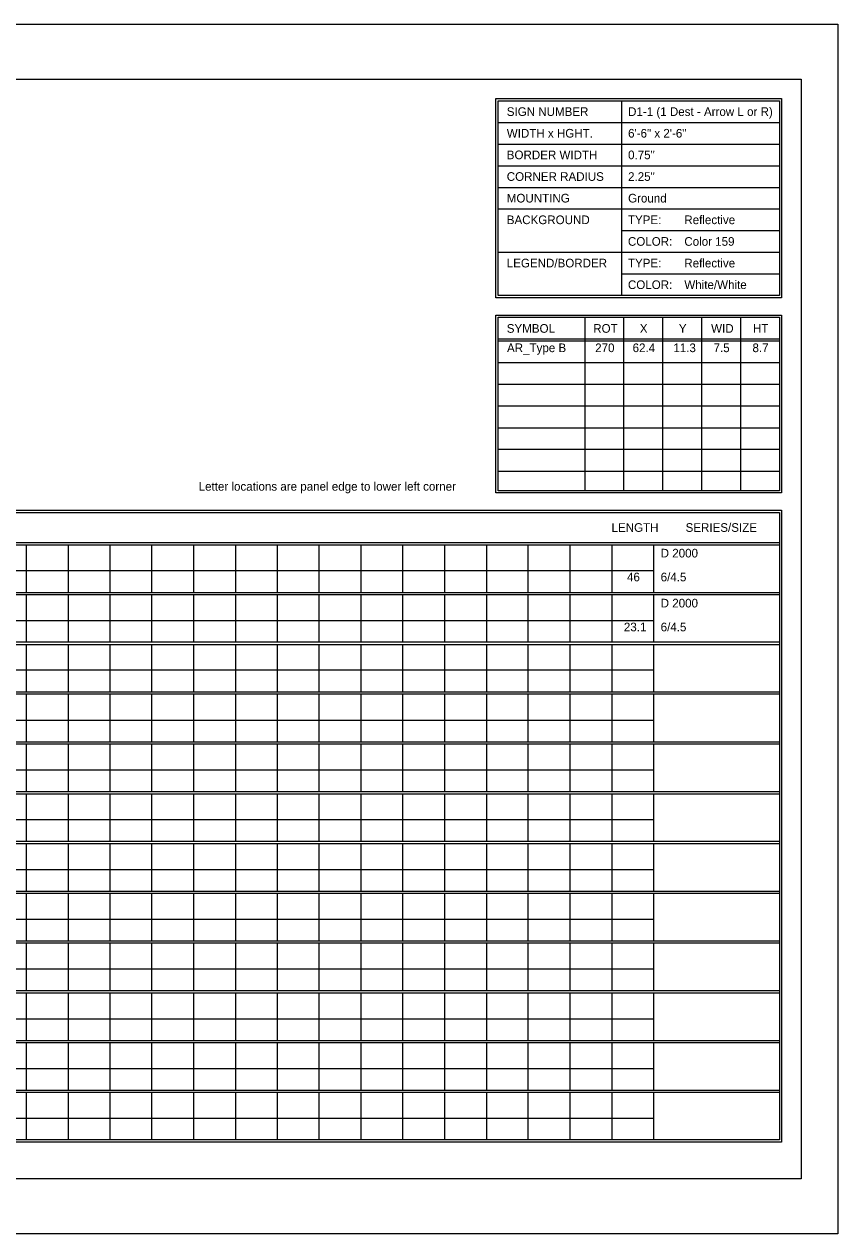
# Model space of a CAD drawing. Extents: x 1806251 to 1809821, y 414895 to 422886.
# Drawn here: x 1809679.34 to 1809684.89, y 415065.97 to 415074.23 of the extents above; entities that cross this region are included whole.
import ezdxf

# ---------------------------------------------------------------- set-up
doc = ezdxf.new("R2010")
doc.units = 0
doc.layers.add('GSSHT', color=7, linetype='Continuous')

msp = doc.modelspace()

# ---------------------------------------------------------------- linework, layer by layer
at = {"layer": 'GSSHT'}
for p, q in [((1809672.1349, 415074.2262), (1809684.8891, 415074.2262)), ((1809684.8891, 415074.2262), (1809684.8891, 415065.9725)), ((1809683.4126, 415073.7035), (1809683.4126, 415072.3747)), ((1809682.571, 415073.5559), (1809684.4905, 415073.5559)), ((1809682.571, 415073.4082), (1809684.4905, 415073.4082)), ((1809682.571, 415073.2606), (1809684.4905, 415073.2606)), ((1809682.571, 415073.1129), (1809684.4905, 415073.1129)), ((1809682.571, 415072.9653), (1809684.4905, 415072.9653)), ((1809683.4126, 415072.8176), (1809684.4905, 415072.8176)), ((1809682.571, 415072.67), (1809684.4905, 415072.67)), ((1809683.4126, 415072.5223), (1809684.4905, 415072.5223)), ((1809683.1616, 415072.227), (1809683.1616, 415071.0428)), ((1809683.4274, 415072.227), (1809683.4274, 415071.0428)), ((1809683.6931, 415072.227), (1809683.6931, 415071.0428)), ((1809683.9589, 415072.227), (1809683.9589, 415071.0428)), ((1809684.2247, 415072.227), (1809684.2247, 415071.0428)), ((1809682.571, 415072.0794), (1809684.4905, 415072.0794)), ((1809682.571, 415072.0646), (1809684.4905, 415072.0646)), ((1809682.571, 415071.9169), (1809684.4905, 415071.9169)), ((1809682.571, 415071.7693), (1809684.4905, 415071.7693)), ((1809682.571, 415071.6216), (1809684.4905, 415071.6216)), ((1809682.571, 415071.471), (1809684.4905, 415071.471)), ((1809682.571, 415071.3263), (1809684.4905, 415071.3263)), ((1809682.571, 415071.1757), (1809684.4905, 415071.1757)), ((1809672.7816, 415070.6885), (1809684.4905, 415070.6885)), ((1809672.7816, 415070.6737), (1809684.4905, 415070.6737)), ((1809679.3492, 415070.6737), (1809679.3492, 415070.3489)), ((1809679.6357, 415070.6737), (1809679.6357, 415070.3489)), ((1809679.9221, 415070.6737), (1809679.9221, 415070.3489)), ((1809680.2056, 415070.6737), (1809680.2056, 415070.3489)), ((1809680.492, 415070.6737), (1809680.492, 415070.3489)), ((1809680.7785, 415070.6737), (1809680.7785, 415070.3489)), ((1809681.062, 415070.6737), (1809681.062, 415070.3489)), ((1809681.3484, 415070.6737), (1809681.3484, 415070.3489)), ((1809681.6349, 415070.6737), (1809681.6349, 415070.3489)), ((1809681.9184, 415070.6737), (1809681.9184, 415070.3489)), ((1809682.2048, 415070.6737), (1809682.2048, 415070.3489)), ((1809682.4913, 415070.6737), (1809682.4913, 415070.3489)), ((1809682.7747, 415070.6737), (1809682.7747, 415070.3489)), ((1809683.0612, 415070.6737), (1809683.0612, 415070.3489)), ((1809683.3476, 415070.6737), (1809683.3476, 415070.3489)), ((1809683.6311, 415070.6737), (1809683.6311, 415070.3489)), ((1809672.7816, 415070.4995), (1809683.6311, 415070.4995)), ((1809672.7816, 415070.3489), (1809684.4905, 415070.3489)), ((1809672.7816, 415070.3341), (1809684.4905, 415070.3341)), ((1809679.3492, 415070.3341), (1809679.3492, 415070.0122)), ((1809679.6357, 415070.3341), (1809679.6357, 415070.0122)), ((1809679.9221, 415070.3341), (1809679.9221, 415070.0122)), ((1809680.2056, 415070.3341), (1809680.2056, 415070.0122)), ((1809680.492, 415070.3341), (1809680.492, 415070.0122)), ((1809680.7785, 415070.3341), (1809680.7785, 415070.0122)), ((1809681.062, 415070.3341), (1809681.062, 415070.0122)), ((1809681.3484, 415070.3341), (1809681.3484, 415070.0122)), ((1809681.6349, 415070.3341), (1809681.6349, 415070.0122)), ((1809681.9184, 415070.3341), (1809681.9184, 415070.0122)), ((1809682.2048, 415070.3341), (1809682.2048, 415070.0122)), ((1809682.4913, 415070.3341), (1809682.4913, 415070.0122)), ((1809682.7747, 415070.3341), (1809682.7747, 415070.0122)), ((1809683.0612, 415070.3341), (1809683.0612, 415070.0122)), ((1809683.3476, 415070.3341), (1809683.3476, 415070.0122)), ((1809683.6311, 415070.3341), (1809683.6311, 415070.0122)), ((1809672.7816, 415070.1569), (1809683.6311, 415070.1569)), ((1809672.7816, 415070.0122), (1809684.4905, 415070.0122)), ((1809672.7816, 415069.9945), (1809684.4905, 415069.9945)), ((1809679.3492, 415069.9945), (1809679.3492, 415069.6697)), ((1809679.6357, 415069.9945), (1809679.6357, 415069.6697)), ((1809679.9221, 415069.9945), (1809679.9221, 415069.6697)), ((1809680.2056, 415069.9945), (1809680.2056, 415069.6697)), ((1809680.492, 415069.9945), (1809680.492, 415069.6697)), ((1809680.7785, 415069.9945), (1809680.7785, 415069.6697)), ((1809681.062, 415069.9945), (1809681.062, 415069.6697)), ((1809681.3484, 415069.9945), (1809681.3484, 415069.6697)), ((1809681.6349, 415069.9945), (1809681.6349, 415069.6697)), ((1809681.9184, 415069.9945), (1809681.9184, 415069.6697)), ((1809682.2048, 415069.9945), (1809682.2048, 415069.6697)), ((1809682.4913, 415069.9945), (1809682.4913, 415069.6697)), ((1809682.7747, 415069.9945), (1809682.7747, 415069.6697)), ((1809683.0612, 415069.9945), (1809683.0612, 415069.6697)), ((1809683.3476, 415069.9945), (1809683.3476, 415069.6697)), ((1809683.6311, 415069.9945), (1809683.6311, 415069.6697)), ((1809672.7816, 415069.8203), (1809683.6311, 415069.8203)), ((1809672.7816, 415069.6697), (1809684.4905, 415069.6697)), ((1809672.7816, 415069.6579), (1809684.4905, 415069.6579)), ((1809679.3492, 415069.6579), (1809679.3492, 415069.3301)), ((1809679.6357, 415069.6579), (1809679.6357, 415069.3301)), ((1809679.9221, 415069.6579), (1809679.9221, 415069.3301)), ((1809680.2056, 415069.6579), (1809680.2056, 415069.3301)), ((1809680.492, 415069.6579), (1809680.492, 415069.3301)), ((1809680.7785, 415069.6579), (1809680.7785, 415069.3301)), ((1809681.062, 415069.6579), (1809681.062, 415069.3301)), ((1809681.3484, 415069.6579), (1809681.3484, 415069.3301)), ((1809681.6349, 415069.6579), (1809681.6349, 415069.3301)), ((1809681.9184, 415069.6579), (1809681.9184, 415069.3301)), ((1809682.2048, 415069.6579), (1809682.2048, 415069.3301)), ((1809682.4913, 415069.6579), (1809682.4913, 415069.3301)), ((1809682.7747, 415069.6579), (1809682.7747, 415069.3301)), ((1809683.0612, 415069.6579), (1809683.0612, 415069.3301)), ((1809683.3476, 415069.6579), (1809683.3476, 415069.3301)), ((1809683.6311, 415069.6579), (1809683.6311, 415069.3301)), ((1809672.7816, 415069.4777), (1809683.6311, 415069.4777)), ((1809672.7816, 415069.3301), (1809684.4905, 415069.3301)), ((1809672.7816, 415069.3153), (1809684.4905, 415069.3153)), ((1809679.3492, 415069.3153), (1809679.3492, 415068.9905)), ((1809679.6357, 415069.3153), (1809679.6357, 415068.9905)), ((1809679.9221, 415069.3153), (1809679.9221, 415068.9905)), ((1809680.2056, 415069.3153), (1809680.2056, 415068.9905)), ((1809680.492, 415069.3153), (1809680.492, 415068.9905)), ((1809680.7785, 415069.3153), (1809680.7785, 415068.9905)), ((1809681.062, 415069.3153), (1809681.062, 415068.9905)), ((1809681.3484, 415069.3153), (1809681.3484, 415068.9905)), ((1809681.6349, 415069.3153), (1809681.6349, 415068.9905)), ((1809681.9184, 415069.3153), (1809681.9184, 415068.9905)), ((1809682.2048, 415069.3153), (1809682.2048, 415068.9905)), ((1809682.4913, 415069.3153), (1809682.4913, 415068.9905)), ((1809682.7747, 415069.3153), (1809682.7747, 415068.9905)), ((1809683.0612, 415069.3153), (1809683.0612, 415068.9905)), ((1809683.3476, 415069.3153), (1809683.3476, 415068.9905)), ((1809683.6311, 415069.3153), (1809683.6311, 415068.9905)), ((1809672.7816, 415069.1381), (1809683.6311, 415069.1381)), ((1809672.7816, 415068.9905), (1809684.4905, 415068.9905)), ((1809672.7816, 415068.9757), (1809684.4905, 415068.9757)), ((1809679.3492, 415068.9757), (1809679.3492, 415068.6509)), ((1809679.6357, 415068.9757), (1809679.6357, 415068.6509)), ((1809679.9221, 415068.9757), (1809679.9221, 415068.6509)), ((1809680.2056, 415068.9757), (1809680.2056, 415068.6509)), ((1809680.492, 415068.9757), (1809680.492, 415068.6509)), ((1809680.7785, 415068.9757), (1809680.7785, 415068.6509)), ((1809681.062, 415068.9757), (1809681.062, 415068.6509)), ((1809681.3484, 415068.9757), (1809681.3484, 415068.6509)), ((1809681.6349, 415068.9757), (1809681.6349, 415068.6509)), ((1809681.9184, 415068.9757), (1809681.9184, 415068.6509)), ((1809682.2048, 415068.9757), (1809682.2048, 415068.6509)), ((1809682.4913, 415068.9757), (1809682.4913, 415068.6509)), ((1809682.7747, 415068.9757), (1809682.7747, 415068.6509)), ((1809683.0612, 415068.9757), (1809683.0612, 415068.6509)), ((1809683.3476, 415068.9757), (1809683.3476, 415068.6509)), ((1809683.6311, 415068.9757), (1809683.6311, 415068.6509)), ((1809672.7816, 415068.7985), (1809683.6311, 415068.7985)), ((1809672.7816, 415068.6509), (1809684.4905, 415068.6509)), ((1809672.7816, 415068.6361), (1809684.4905, 415068.6361)), ((1809679.3492, 415068.6361), (1809679.3492, 415068.3113)), ((1809679.6357, 415068.6361), (1809679.6357, 415068.3113)), ((1809679.9221, 415068.6361), (1809679.9221, 415068.3113)), ((1809680.2056, 415068.6361), (1809680.2056, 415068.3113)), ((1809680.492, 415068.6361), (1809680.492, 415068.3113)), ((1809680.7785, 415068.6361), (1809680.7785, 415068.3113)), ((1809681.062, 415068.6361), (1809681.062, 415068.3113)), ((1809681.3484, 415068.6361), (1809681.3484, 415068.3113)), ((1809681.6349, 415068.6361), (1809681.6349, 415068.3113)), ((1809681.9184, 415068.6361), (1809681.9184, 415068.3113)), ((1809682.2048, 415068.6361), (1809682.2048, 415068.3113)), ((1809682.4913, 415068.6361), (1809682.4913, 415068.3113)), ((1809682.7747, 415068.6361), (1809682.7747, 415068.3113)), ((1809683.0612, 415068.6361), (1809683.0612, 415068.3113)), ((1809683.3476, 415068.6361), (1809683.3476, 415068.3113)), ((1809683.6311, 415068.6361), (1809683.6311, 415068.3113)), ((1809672.7816, 415068.4589), (1809683.6311, 415068.4589)), ((1809672.7816, 415068.3113), (1809684.4905, 415068.3113)), ((1809672.7816, 415068.2965), (1809684.4905, 415068.2965)), ((1809679.3492, 415068.2965), (1809679.3492, 415067.9717)), ((1809679.6357, 415068.2965), (1809679.6357, 415067.9717)), ((1809679.9221, 415068.2965), (1809679.9221, 415067.9717)), ((1809680.2056, 415068.2965), (1809680.2056, 415067.9717)), ((1809680.492, 415068.2965), (1809680.492, 415067.9717)), ((1809680.7785, 415068.2965), (1809680.7785, 415067.9717)), ((1809681.062, 415068.2965), (1809681.062, 415067.9717)), ((1809681.3484, 415068.2965), (1809681.3484, 415067.9717)), ((1809681.6349, 415068.2965), (1809681.6349, 415067.9717)), ((1809681.9184, 415068.2965), (1809681.9184, 415067.9717)), ((1809682.2048, 415068.2965), (1809682.2048, 415067.9717)), ((1809682.4913, 415068.2965), (1809682.4913, 415067.9717)), ((1809682.7747, 415068.2965), (1809682.7747, 415067.9717)), ((1809683.0612, 415068.2965), (1809683.0612, 415067.9717)), ((1809683.3476, 415068.2965), (1809683.3476, 415067.9717)), ((1809683.6311, 415068.2965), (1809683.6311, 415067.9717)), ((1809672.7816, 415068.1193), (1809683.6311, 415068.1193)), ((1809672.7816, 415067.9717), (1809684.4905, 415067.9717)), ((1809672.7816, 415067.9569), (1809684.4905, 415067.9569)), ((1809679.3492, 415067.9569), (1809679.3492, 415067.6321)), ((1809679.6357, 415067.9569), (1809679.6357, 415067.6321)), ((1809679.9221, 415067.9569), (1809679.9221, 415067.6321)), ((1809680.2056, 415067.9569), (1809680.2056, 415067.6321)), ((1809680.492, 415067.9569), (1809680.492, 415067.6321)), ((1809680.7785, 415067.9569), (1809680.7785, 415067.6321)), ((1809681.062, 415067.9569), (1809681.062, 415067.6321)), ((1809681.3484, 415067.9569), (1809681.3484, 415067.6321)), ((1809681.6349, 415067.9569), (1809681.6349, 415067.6321)), ((1809681.9184, 415067.9569), (1809681.9184, 415067.6321)), ((1809682.2048, 415067.9569), (1809682.2048, 415067.6321)), ((1809682.4913, 415067.9569), (1809682.4913, 415067.6321)), ((1809682.7747, 415067.9569), (1809682.7747, 415067.6321)), ((1809683.0612, 415067.9569), (1809683.0612, 415067.6321)), ((1809683.3476, 415067.9569), (1809683.3476, 415067.6321)), ((1809683.6311, 415067.9569), (1809683.6311, 415067.6321)), ((1809672.7816, 415067.7797), (1809683.6311, 415067.7797)), ((1809672.7816, 415067.6321), (1809684.4905, 415067.6321)), ((1809672.7816, 415067.6173), (1809684.4905, 415067.6173)), ((1809679.3492, 415067.6173), (1809679.3492, 415067.2925)), ((1809679.6357, 415067.6173), (1809679.6357, 415067.2925)), ((1809679.9221, 415067.6173), (1809679.9221, 415067.2925)), ((1809680.2056, 415067.6173), (1809680.2056, 415067.2925)), ((1809680.492, 415067.6173), (1809680.492, 415067.2925)), ((1809680.7785, 415067.6173), (1809680.7785, 415067.2925)), ((1809681.062, 415067.6173), (1809681.062, 415067.2925)), ((1809681.3484, 415067.6173), (1809681.3484, 415067.2925)), ((1809681.6349, 415067.6173), (1809681.6349, 415067.2925)), ((1809681.9184, 415067.6173), (1809681.9184, 415067.2925)), ((1809682.2048, 415067.6173), (1809682.2048, 415067.2925)), ((1809682.4913, 415067.6173), (1809682.4913, 415067.2925)), ((1809682.7747, 415067.6173), (1809682.7747, 415067.2925)), ((1809683.0612, 415067.6173), (1809683.0612, 415067.2925)), ((1809683.3476, 415067.6173), (1809683.3476, 415067.2925)), ((1809683.6311, 415067.6173), (1809683.6311, 415067.2925)), ((1809672.7816, 415067.4401), (1809683.6311, 415067.4401)), ((1809672.7816, 415067.2925), (1809684.4905, 415067.2925)), ((1809672.7816, 415067.2777), (1809684.4905, 415067.2777)), ((1809679.3492, 415067.2777), (1809679.3492, 415066.9529)), ((1809679.6357, 415067.2777), (1809679.6357, 415066.9529)), ((1809679.9221, 415067.2777), (1809679.9221, 415066.9529)), ((1809680.2056, 415067.2777), (1809680.2056, 415066.9529)), ((1809680.492, 415067.2777), (1809680.492, 415066.9529)), ((1809680.7785, 415067.2777), (1809680.7785, 415066.9529)), ((1809681.062, 415067.2777), (1809681.062, 415066.9529)), ((1809681.3484, 415067.2777), (1809681.3484, 415066.9529)), ((1809681.6349, 415067.2777), (1809681.6349, 415066.9529)), ((1809681.9184, 415067.2777), (1809681.9184, 415066.9529)), ((1809682.2048, 415067.2777), (1809682.2048, 415066.9529)), ((1809682.4913, 415067.2777), (1809682.4913, 415066.9529)), ((1809682.7747, 415067.2777), (1809682.7747, 415066.9529)), ((1809683.0612, 415067.2777), (1809683.0612, 415066.9529)), ((1809683.3476, 415067.2777), (1809683.3476, 415066.9529)), ((1809683.6311, 415067.2777), (1809683.6311, 415066.9529)), ((1809672.7816, 415067.1005), (1809683.6311, 415067.1005)), ((1809672.7816, 415066.9529), (1809684.4905, 415066.9529)), ((1809672.7816, 415066.9381), (1809684.4905, 415066.9381)), ((1809679.3492, 415066.9381), (1809679.3492, 415066.6133)), ((1809679.6357, 415066.9381), (1809679.6357, 415066.6133)), ((1809679.9221, 415066.9381), (1809679.9221, 415066.6133)), ((1809680.2056, 415066.9381), (1809680.2056, 415066.6133)), ((1809680.492, 415066.9381), (1809680.492, 415066.6133)), ((1809680.7785, 415066.9381), (1809680.7785, 415066.6133)), ((1809681.062, 415066.9381), (1809681.062, 415066.6133)), ((1809681.3484, 415066.9381), (1809681.3484, 415066.6133)), ((1809681.6349, 415066.9381), (1809681.6349, 415066.6133)), ((1809681.9184, 415066.9381), (1809681.9184, 415066.6133)), ((1809682.2048, 415066.9381), (1809682.2048, 415066.6133)), ((1809682.4913, 415066.9381), (1809682.4913, 415066.6133)), ((1809682.7747, 415066.9381), (1809682.7747, 415066.6133)), ((1809683.0612, 415066.9381), (1809683.0612, 415066.6133)), ((1809683.3476, 415066.9381), (1809683.3476, 415066.6133)), ((1809683.6311, 415066.9381), (1809683.6311, 415066.6133)), ((1809672.7816, 415066.7609), (1809683.6311, 415066.7609)), ((1809684.8891, 415065.9725), (1809672.1349, 415065.9725))]:
    msp.add_line(p, q, dxfattribs=at)
for points in [[(1809672.634, 415073.8512), (1809684.6381, 415073.8512), (1809684.6381, 415066.3475), (1809672.634, 415066.3475)], [(1809682.5562, 415073.7183), (1809684.5052, 415073.7183), (1809684.5052, 415072.3599), (1809682.5562, 415072.3599)], [(1809682.571, 415073.7035), (1809684.4905, 415073.7035), (1809684.4905, 415072.3747), (1809682.571, 415072.3747)], [(1809682.5562, 415072.2418), (1809684.5052, 415072.2418), (1809684.5052, 415071.0281), (1809682.5562, 415071.0281)], [(1809682.571, 415072.227), (1809684.4905, 415072.227), (1809684.4905, 415071.0428), (1809682.571, 415071.0428)], [(1809672.7669, 415070.91), (1809684.5052, 415070.91), (1809684.5052, 415066.5985), (1809672.7669, 415066.5985)], [(1809672.7816, 415070.8952), (1809684.4905, 415070.8952), (1809684.4905, 415066.6133), (1809672.7816, 415066.6133)]]:
    msp.add_lwpolyline(points, close=True, dxfattribs=at)

# ---------------------------------------------------------------- texts
for s, height, p in [('SIGN NUMBER', 0.059055, (1809682.63, 415073.6002)), ('D1-1 (1 Dest - Arrow L or R)', 0.059055, (1809683.4579, 415073.6001)), ('WIDTH x HGHT.', 0.059055, (1809682.63, 415073.4525)), ('6\'-6" x 2\'-6"', 0.059055, (1809683.4579, 415073.4524)), ('BORDER WIDTH', 0.059055, (1809682.63, 415073.3049)), ('0.75"', 0.05906, (1809683.4579, 415073.3048)), ('CORNER RADIUS', 0.059055, (1809682.63, 415073.1572)), ('2.25"', 0.05906, (1809683.4579, 415073.1571)), ('MOUNTING', 0.05906, (1809682.63, 415073.0096)), ('Ground', 0.05906, (1809683.4579, 415073.0095)), ('BACKGROUND', 0.05906, (1809682.63, 415072.8619)), ('TYPE:', 0.05906, (1809683.4569, 415072.8619)), ('Reflective', 0.05906, (1809683.8418, 415072.8619)), ('COLOR:', 0.05906, (1809683.4569, 415072.7143)), ('Color 159', 0.05906, (1809683.8418, 415072.7142)), ('LEGEND/BORDER', 0.059055, (1809682.63, 415072.5666)), ('TYPE:', 0.05906, (1809683.4569, 415072.5666)), ('Reflective', 0.05906, (1809683.8418, 415072.5666)), ('COLOR:', 0.05906, (1809683.4569, 415072.419)), ('White/White', 0.059055, (1809683.8418, 415072.419)), ('SYMBOL', 0.05906, (1809682.63, 415072.1207)), ('ROT', 0.05906, (1809683.22, 415072.1207)), ('X', 0.0591, (1809683.538, 415072.1207)), ('Y', 0.0591, (1809683.8041, 415072.1207)), ('WID', 0.05906, (1809684.0246, 415072.1207)), ('HT', 0.05906, (1809684.3102, 415072.1207)), ('AR_Type B', 0.05906, (1809682.6317, 415071.9885)), ('270', 0.05906, (1809683.2333, 415071.9885)), ('62.4', 0.05906, (1809683.4888, 415071.9885)), ('11.3', 0.05906, (1809683.7668, 415071.9885)), ('7.5', 0.05906, (1809684.0413, 415071.9885)), ('8.7', 0.05906, (1809684.3067, 415071.9885)), ('Letter locations are panel edge to lower left corner', 0.059055, (1809680.5272, 415071.043)), ('LENGTH', 0.05906, (1809683.345, 415070.7623)), ('SERIES/SIZE', 0.059061, (1809683.8502, 415070.7623)), ('D 2000', 0.05906, (1809683.6803, 415070.5874)), ('46', 0.05906, (1809683.4507, 415070.4246)), ('6/4.5', 0.05906, (1809683.6803, 415070.4246)), ('D 2000', 0.05906, (1809683.6803, 415070.2463)), ('23.1', 0.05906, (1809683.4292, 415070.0835)), ('6/4.5', 0.05906, (1809683.6803, 415070.0835))]:
    msp.add_text(s, height=height, dxfattribs=at).set_placement(p)

doc.saveas('drawing.dxf')
